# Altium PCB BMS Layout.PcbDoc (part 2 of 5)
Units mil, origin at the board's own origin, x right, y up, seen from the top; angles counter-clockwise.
Board outline 5576.78 x 4051.82 mil, 6 copper layers (Top Layer, GND1, Analog Signal, Power, GND2, Bottom Layer), stack 61.2 mil thick; 425 components, 206 nets, 1164 pads, 390 vias.
Unrouted connection lines stored in the file: 32.
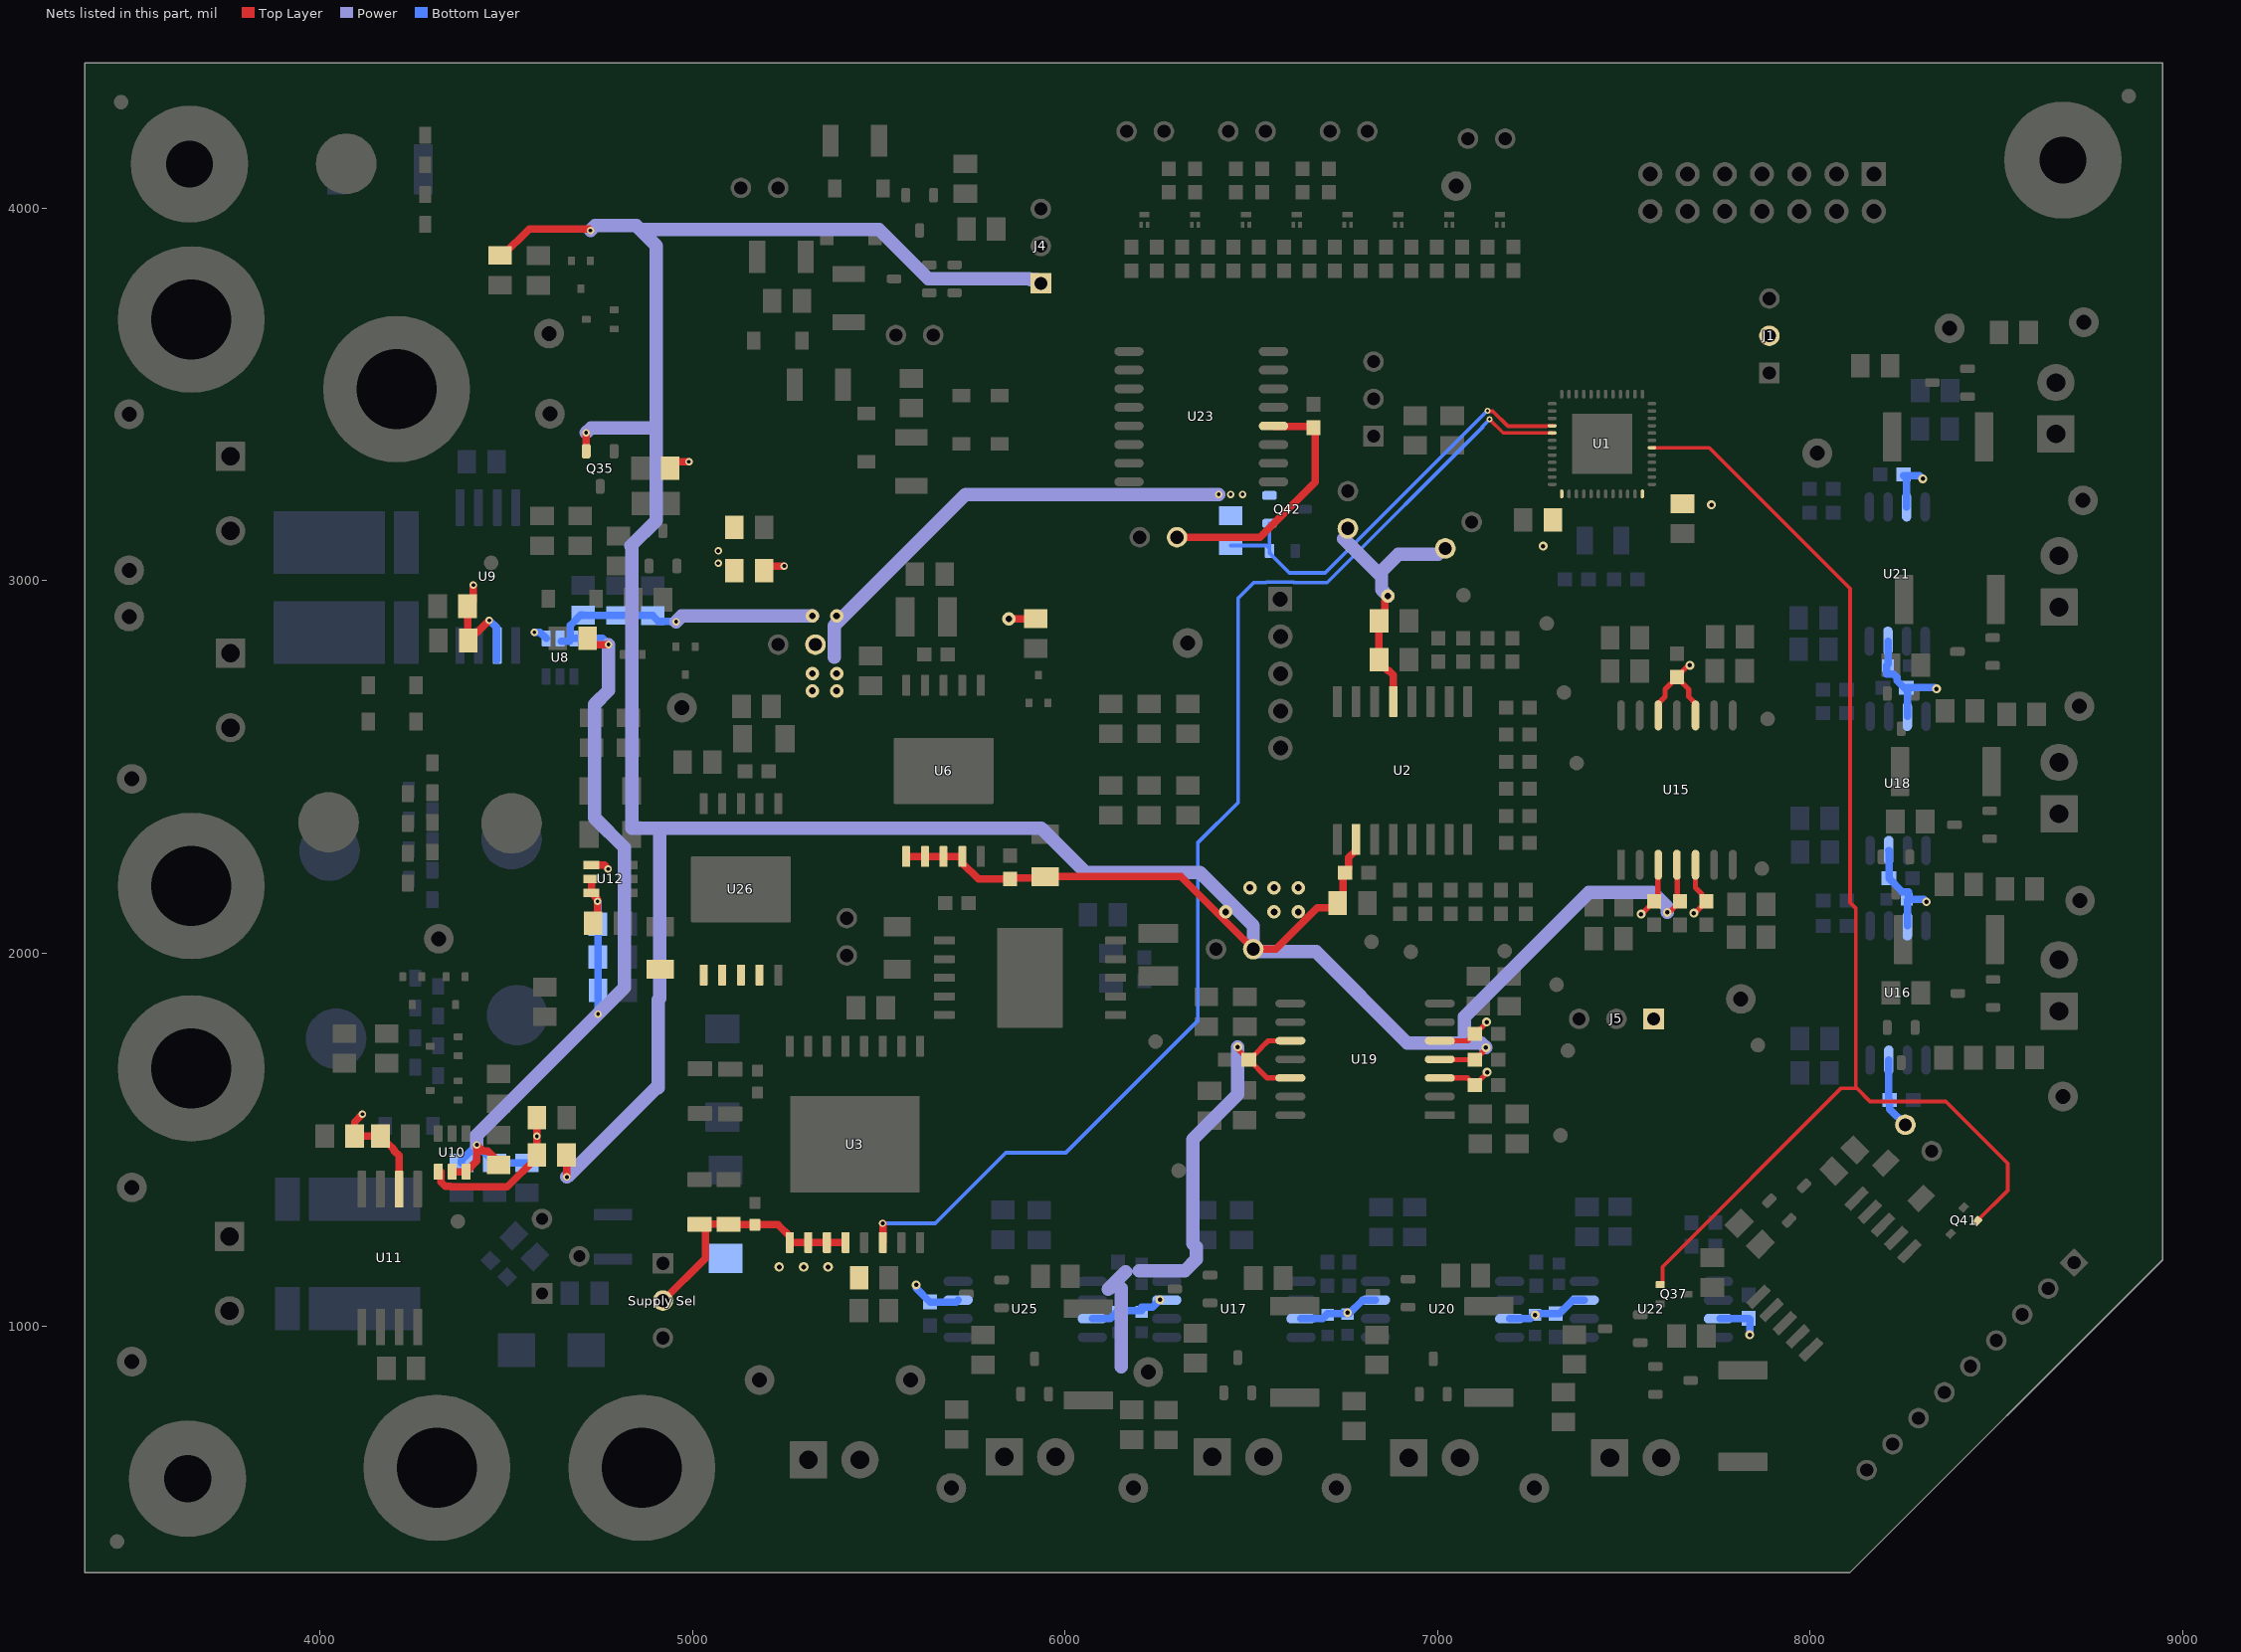
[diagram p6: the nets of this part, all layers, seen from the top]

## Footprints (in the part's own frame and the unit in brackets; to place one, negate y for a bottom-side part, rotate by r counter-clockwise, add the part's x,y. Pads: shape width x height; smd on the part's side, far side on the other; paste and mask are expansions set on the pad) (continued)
RGZ0048B_NV [mm] "QFN, 48-Leads, Body 7x7mm, Pitch 0.5mm, Thermal Pad 5.15x5.15mm, TI Recommended"
  oval 0.6x0.24 smd: 1(-3.4,2.75) 2(-3.4,2.25) 3(-3.4,1.75) 4(-3.4,1.25) 5(-3.4,0.75) 6(-3.4,0.25) 7(-3.4,-0.25) 8(-3.4,-0.75) 9(-3.4,-1.25) 10(-3.4,-1.75) 11(-3.4,-2.25) 12(-3.4,-2.75) 25(3.4,-2.75) 26(3.4,-2.25) 27(3.4,-1.75) 28(3.4,-1.25) 29(3.4,-0.75) 30(3.4,-0.25) 31(3.4,0.25) 32(3.4,0.75) 33(3.4,1.25) 34(3.4,1.75) 35(3.4,2.25) 36(3.4,2.75)
  oval 0.24x0.6 smd: 13(-2.75,-3.4) 14(-2.25,-3.4) 15(-1.75,-3.4) 16(-1.25,-3.4) 17(-0.75,-3.4) 18(-0.25,-3.4) 19(0.25,-3.4) 20(0.75,-3.4) 21(1.25,-3.4) 22(1.75,-3.4) 23(2.25,-3.4) 24(2.75,-3.4) 37(2.75,3.4) 38(2.25,3.4) 39(1.75,3.4) 40(1.25,3.4) 41(0.75,3.4) 42(0.25,3.4) 43(-0.25,3.4) 44(-0.75,3.4) 45(-1.25,3.4) 46(-1.75,3.4) 47(-2.25,3.4) 48(-2.75,3.4)
  rect 4.1x4.1 smd paste-2.575: 49(0,0)
  silkscreen extent -3.72,-3.72 3.72,3.72, body extent -3.57,-3.58 3.58,3.57, height 1.01
SOD-123 [mm] "On Semi recommended land pattern"
  rect 0.915x1.22 smd: 1(-1.637,0) 2(1.637,0)
  silkscreen extent -2.74,-1.17 2.03,1.17, body extent -1.93,-0.9 1.93,0.9, height 1.35
SOD-123FL [mm] "Copied from SOD-123"
  rect 0.915x1.22 smd: 1(-1.637,0) 2(1.637,0)
  silkscreen extent -2.74,-1.16 1.68,1.16, body extent -1.9,-0.9 1.9,0.9, height 1
SOT-23 [mm] "SOT23, 3-Leads, Body 2.9x1.3mm, Pitch 0.95mm, Lead Span 2.5mm, IPC Medium Density"
  rrect50% 1x0.6 smd: 1(-1.2,0.95) 2(-1.2,-0.95) 3(1.2,0)
  silkscreen extent -1.63,-1.5 0.7,1.5, body extent -1.16,-1.45 1.21,1.45, height 1
SOT-323 [mm] "Diodes Inc recommended land pattern.  2016-02-24"
  rrect21% 0.6x0.47 smd: 1(-0.95,0.65) 2(-0.95,-0.65) 3(0.95,0)
  silkscreen extent -1.14,-1.22 0.77,1.22, body extent -1.13,-1.13 1.12,1.12, height 1.13
TERM_BLK_ED555-2DS [mil]
  rrect4% 100x100 hole 50: 1(0,0)
  round 100 hole 50: 2(138,0)
  silkscreen extent -93,-161 215,113, body extent -69,-150 207,106, height 323
TI_Symbol_Overlay_Small [mil]
  silkscreen extent -90,-88 91,88
TP_SM_1MM [mm] "1mm Test Point, SMT"
  round 1 smd paste-0.5: 1(0,0)
TSW-105-07-X-S [mm] "Samtec 100mil, 1x5, 230 mil above insulator"
  rrect6% 1.65x1.65 hole 1.016: 1(-5.08,-0.025)
  round 1.65 hole 1.016: 2(-2.54,0) 3(0,0) 4(2.54,0) 5(5.08,0)
  silkscreen extent -7.05,-1.25 6.37,1.25, body extent -6.35,-1.27 6.35,1.27, height 8.38
WEEE_Minimum [mil] "WEEElie bin"
  silkscreen extent -95,-172 99,104
WSL3637_0.001 [mil] "Vishay WSL3637 recommended land pattern for 0.001 to 0.0019 Ohm"
  rect 168x300 smd: 1(-121,-45) 2(121,-45)
  rect 168x66 smd: 3(-121,162) 4(121,162)
  silkscreen extent -220,-210 220,210, body extent -185,-190 185,190, height 35
WSL3637_0_002 [mil] "Vishay WSL3637 recommended land pattern for 0.002 to 0.01 Ohm"
  rect 116x300 smd: 1(-147,-45) 2(147,-45)
  rect 116x66 smd: 3(-147,162) 4(147,162)
  silkscreen extent -220,-210 220,210, body extent -185,-190 185,190, height 35

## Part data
"12V Supply" Batt_1 Batt_2 Batt_3 Batt_4 Batt_5 Batt_6 Batt_7 Batt_8: library part CMP-0074913-1, "Terminal Block, 3.5mm Pitch, 2x1, TH", Color=Grey, Current_A=6A, Manufacturer="On-Shore Technology", Supplier Part Number 1=ED1514-ND, Voltage_V=150V
Batt Charger Load: library part CMP-0074910-1, "Terminal Block, 5.08 mm, 2x1, Brass, TH", Color=Blue, Current_A=15A, Manufacturer="On-Shore Technology", Supplier Part Number 1=ED1609-ND, Voltage_V=300V
Batt_ Charger_ GND GND_ Load_ LOAD_GND: library part CMP-0055166-1, "Standard Banana Jack, Uninsulated, 8.9mm", Manufacturer=Keystone, Supplier Part Number 1=36-575-8-ND
C1 C7: library part CMP-0007731-1, "CAP, CERM, 1 uF, 10 V, +/- 10%, X7R, 0805", Cap_Case=0805, Manufacturer=Kemet, Supplier Part Number 1=399-1172-1-ND, TempCo=X7R, Tolerance_%=10%, Value1="0.015 ohm", Value2=10V, ValueDisplayed=1uF
C2 C6 C8: library part CMP-0012474-2, "CAP, Film, 0.1 uF, 16 V, +/- 20%, 0805 SMD", Cap_Case=0805, Manufacturer=Panasonic, Supplier Part Number 1=PCF1126CT-ND, Tolerance_%=20%, Value1=Unknown, Value2=16V, ValueDisplayed=0.1uF
C3 C4: library part CMP-0006839-1, "CAP, CERM, 10 pF, 50 V, +/- 5%, C0G/NP0, 0603", Cap_Case=0603, Manufacturer=Kemet, Supplier Part Number 1=399-1049-1-ND, TempCo=C0G/NP0, Tolerance_%=5%, Value1=Unknown, Value2=50V, ValueDisplayed=10pF
C5: library part CMP-0079607-1, "CAP, CERM, 1 µF, 16 V,+/- 10%, X7R, AEC-Q200 Grade 1, 0603", Cap_Case=0603, Manufacturer=TDK, Supplier Part Number 1=445-12539-1-ND, TempCo=X7R, Tolerance_%=10%, Value2=16V, ValueDisplayed=1µF
C9: library part CMP-0007581-2, "CAP, CERM, 1000 pF, 50 V, +/- 1%, C0G/NP0, 0805", Cap_Case=0805, Manufacturer=AVX, Supplier Part Number 1=478-3759-1-ND, TempCo=C0G/NP0, Tolerance_%=1%, Value1="0.112 ohm", Value2=50V, ValueDisplayed=1000pF
C10 C14 C20 C22: library part CMP-0093201-1, "10 µF ±10% 50V Ceramic Capacitor X7R 1206 (3216 Metric)", Manufacturer="Cal-Chip Electronics", Operating Temperature Range="-55°C to +125°C", TempCo=15%, Temperature Characteristic=X7R, Tolerance_%=10%, ValueDisplayed=10uF
C11 C15 C17 C25 C26 C33 C114: library part CMP-0006861-3, "CAP, CERM, 0.1 uF, 50 V, +/- 10%, X7R, 0603", Cap_Case=0603, Manufacturer=Kemet, Supplier Part Number 1=399-5089-1-ND, TempCo=X7R, Tolerance_%=10%, Value1=Unknown, Value2=50V, ValueDisplayed=0.1uF
C12 C13: library part CMP-0094511-1, "0.1 µF ±5% 50V Ceramic Capacitor X7R 0603 (1608 Metric)", Digikey Part Number=478-7426-1-ND, Manufacturer="KYOCERA AVX", Mouser Part Number=581-06035C104J4Z2A, Operating Temperature Range=to, TempCo=15%, Temperature Characteristic=X7R, Tolerance_%=5%, ValueDisplayed=0.1uF
C16 C34 C79 C128: library part CMP-0082252-1, "CAP, CERM, 10 µF, 25 V,+/- 20%, X7R, AEC-Q200 Grade 1, 1206", Cap_Case=1206, Manufacturer=MuRata, Supplier Part Number 1=490-6519-1-ND, TempCo=X7R, Tolerance_%=20%, Value2=25V, ValueDisplayed=10µF
C18: library part CMP-2000-06366-1, "Chip Capacitor, 1 uF, +/- 10%, 100 V, -55 to 125 degC, 1210 (3225 Metric), RoHS, Tape and Reel GRM32ER72A105KA01L", Capacitance=1µF, Manufacturer=Murata, Operating Temperature=-55°C~125°C, Package / Case=1210(3225Metric), Package Description="2-Pin Surface Mount Device, Body 3.2 x 2.5 mm", Package Reference=1210, Ratings=-, Standard Package=1, Temperature Coefficient=X7R, Tolerance=±10%, Voltage - Rated=100V
C19 C27: library part CMP-0009190-1, "CAP, CERM, 10 uF, 25 V, +/- 10%, X7R, 1210", Cap_Case=1210, Manufacturer=MuRata, Supplier Part Number 1=490-1867-1-ND, TempCo=X7R, Tolerance_%=10%, Value1=Unknown, Value2=25V, ValueDisplayed=10uF
C21 C23: library part CMP-0093169-1, "150µF Molded Tantalum Polymer Capacitor 20V 2917 (7343 Metric) 50mOhm @ 100kHz", Digikey Part Number=399-19581-1-ND, Leakage Current=300uA, Manufacturer=Kemet, Mouser Part Number=80-T521D157M020ATE50, Operating Temperature Range="-55°C to +105°C", Tolerance_%=20%, ValueDisplayed=150uF
C24: library part CMP-0011596-1, "CAP, TA, 1 uF, 50 V, +/- 10%, 4.6 ohm, SMD", Cap_Case=C, Manufacturer=Vishay-Sprague, Supplier Part Number 1=718-1041-1-ND, Tolerance_%=10%, Value1="4.6 ohm", Value2=50V, ValueDisplayed=1uF
C28 C29 C124 C125 C126: library part CMP-0009164-1, "CAP, CERM, 10 uF, 50 V, +/- 10%, X7S, AEC-Q200 Grade 1, 1210", Cap_Case=1210_280, Manufacturer=TDK, Supplier Part Number 1=445-7004-1-ND, TempCo=X7S, Tolerance_%=10%, Value1="0.002827 ohm", Value2=50V, ValueDisplayed=10uF
C30 C31 C32: library part CMP-0007632-2, "CAP, CERM, 0.1 uF, 50 V, +/- 10%, X7R, 0805", Cap_Case=0805, Manufacturer=AVX, Supplier Part Number 1=478-1395-1-ND, TempCo=X7R, Tolerance_%=10%, Value1="0.024 ohm", Value2=50V, ValueDisplayed=0.1uF
C35 C36: library part CMP-0007900-2, "CAP, CERM, 1 pF, 50 V, +/- 25%, C0G/NP0, 0805", Cap_Case=0805, Manufacturer="Yageo America", Supplier Part Number 1=311-1089-1-ND, TempCo=C0G/NP0, Tolerance_%=25%, Value1=Unknown, Value2=50V, ValueDisplayed=1pF
C37 C40 C42 C45 C47: library part CMP-0008021-2, "CAP, CERM, 0.1 uF, 50 V, +/- 10%, X7R, AEC-Q200 Grade 1, 0805", Cap_Case=0805, Manufacturer=MuRata, Supplier Part Number 1=490-8049-1-ND, TempCo=X7R, Tolerance_%=10%, Value1=Unknown, Value2=50V, ValueDisplayed=0.1uF
C38 C43 C48: library part CMP-0007706-2, "CAP, CERM, 100 pF, 100 V, +/- 5%, X7R, 0805", Cap_Case=0805, Manufacturer=Kemet, Supplier Part Number 1=80-C0805C101J1R, TempCo=X7R, Tolerance_%=5%, Value1=Unknown, Value2=100V, ValueDisplayed=100pF
C39 C44 C49: library part CMP-0080480-1, "CAP, CERM, 1 µF, 50 V,+/- 20%, X7R, AEC-Q200 Grade 1, 0805", Cap_Case=0805, Manufacturer=MuRata, Supplier Part Number 1=490-16470-1-ND, TempCo=X7R, Tolerance_%=20%, Value2=50V, ValueDisplayed=1µF
C41 C46 C53: library part CMP-0008408-2, "CAP, CERM, 0.01 uF, 250 V, +/- 10%, X7R, 0805", Cap_Case=0805, Manufacturer="Taiyo Yuden", Supplier Part Number 1=587-1271-1-ND, TempCo=X7R, Tolerance_%=10%, Value1=Unknown, Value2=250V, ValueDisplayed=0.01uF
C51 C52: library part CMP-0080090-1, "CAP, CERM, 500 pF, 50 V,+/- 2%, C0G/NP0, 0805", Cap_Case=0805, Manufacturer=AVX, Supplier Part Number 1=478-10532-1-ND, TempCo=C0G/NP0, Tolerance_%=2%, Value2=50V, ValueDisplayed=500pF
C84 C85 C92 C93 C97 C101 C102 C106: library part CMP-0008323-2, "CAP, CERM, 1 uF, 16 V, +/- 10%, X7R, 0805", Cap_Case=0805, Manufacturer=MuRata, Supplier Part Number 1=490-1691-1-ND, TempCo=X7R, Tolerance_%=10%, Value1="0.003 ohm", Value2=16V, ValueDisplayed=1uF
C86 C89 C94 C98 C103 C108 C111 C152: library part CMP-0006797-3, "CAP, CERM, 680 pF, 50 V, +/- 1%, C0G/NP0, 0603", Cap_Case=0603, Manufacturer=AVX, Supplier Part Number 1=478-6033-1-ND, TempCo=C0G/NP0, Tolerance_%=1%, Value1=Unknown, Value2=50V, ValueDisplayed=680pF
C87 C90 C95 C99 C104 C107 C109 C153 C154: library part CMP-0007078-4, "CAP, CERM, 0.1 uF, 50 V, +/- 10%, X7R, AEC-Q200 Grade 1, 0603", Cap_Case=0603, Manufacturer=TDK, Supplier Part Number 1=445-5666-1-ND, TempCo=X7R, Tolerance_%=10%, Value1="0.0296 ohm", Value2=50V, ValueDisplayed=0.1uF
C88 C91 C96 C100 C105 C110 C133 C134 C135 C136 C137 C138 C139 C140 C141 C142 C143 C144 C145 C146 C147 C148 C149 C150 C151 C155 C160: library part CMP-0007006-2, "CAP, CERM, 1 uF, 25 V, +/- 10%, X5R, 0603", Cap_Case=0603, Manufacturer=TDK, Supplier Part Number 1=445-5146-1-ND, TempCo=X5R, Tolerance_%=10%, Value1=Unknown, Value2=25V, ValueDisplayed=1uF
C112: library part CMP-0008651-1, "CAP, CERM, 68 uF, 10 V, +/- 20%, X5R, 1206_190", Cap_Case=1206_190, Manufacturer=TDK, Supplier Part Number 1=445-14673-1-ND, TempCo=X5R, Tolerance_%=20%, Value1="0.003494 ohm", Value2=10V, ValueDisplayed=68uF
C115 C116 C117 C118 C119 C120 C121 C156: library part CMP-0006843-4, "CAP, CERM, 1000 pF, 50 V, +/- 5%, C0G/NP0, 0603", Cap_Case=0603, Manufacturer=Kemet, Supplier Part Number 1=399-3293-1-ND, TempCo=C0G/NP0, Tolerance_%=5%, Value1=Unknown, Value2=50V, ValueDisplayed=1000pF
C122 C123: library part CMP-0007632-1, "CAP, CERM, 0.1 uF, 50 V, +/- 10%, X7R, 0805", Cap_Case=0805, Manufacturer=AVX, Supplier Part Number 1=478-1395-1-ND, TempCo=X7R, Tolerance_%=10%, Value1="0.024 ohm", Value2=50V, ValueDisplayed=0.1uF
C164: library part CMP-0091091-1, "Cap Ceramic 0.001uF 250V X7R 10% Pad SMD 0805 Soft Termination 125C Automotive T/R", Digikey Part Number=490-5589-1-ND, Manufacturer=Murata, Mouser Part Number=81-GCJ21AR72E102KX1D, Operating Temperature Range="-55°C to +125°C", TempCo=15%, Temperature Characteristic=X7R, Tolerance_%=10%, ValueDisplayed=1000pF
D1 D2 D3 D7 D8 D9 D10: library part CMP-0077083-2, "Diode, Standard Recovery Rectifier, 200 V, 1 A, SOD-123FL", Manufacturer="Micro Commercial Components", Value1=1A, Value2=1.1V
D4 D5 D6: library part CMP-0005805-3, "Diode, Zener, 6.2 V, 500 mW, SOD-123", Manufacturer="Diodes Inc.", Power_W=500mW, Value1=0.5W
FID1 FID2 FID3: library part CMP-0077181-1, "Fiducial mark.  There is nothing to buy or mount.", Manufacturer=N/A
H1 H2 H4: library part CMP-0003617-1, "Machine Screw, Round, #4-40 x 1/4, Nylon, Philips panhead", Manufacturer="B&F Fastener Supply", Supplier Part Number 1=H542-ND
H5 H6 H8: library part CMP-0003610-1, "Standoff, Hex, 0.5\"L #4-40 Nylon", Manufacturer=Keystone, Supplier Part Number 1=36-1902C-ND
I2C_pull J_1V85 J_2V5 J_3V3 J_3V3_2 J_5V J_heater J_LS J_pump J_PWM Sensor1 Sensor2 Sensor3: library part CMP-0075049-1, "Header, 2.54mm, 2x1, Gold, TH", Manufacturer="Fischer Elektronik"
J1 J4 J5 J6 "Supply Sel": library part CMP-0075048-1, "Header, 2.54mm, 3x1, Gold, TH", Manufacturer="Fischer Elektronik"
J2: library part CMP-0075411-1, "Header, 100mil, 5x1, Gold, TH", Color=Black, Current_A=6.3A, Manufacturer=Samtec, Supplier Part Number 1=SAM1029-05-ND, Voltage_V=550V
J3: library part CMP-0097746-1, "Connector Header Through Hole, Right Angle 9 position 0.098\" (2.50mm)", Current_A=3A, Digikey Part Number=455-2224-ND, Manufacturer=JST, Operating Temperature Range="-25°C to +85°C", Voltage_V=250V
JTAG: library part CMP-0054695-2, "Header (shrouded), 100 mil, 7x2, Gold, TH", Manufacturer="Sullins Connector Solutions", Supplier Part Number 1=S9170-ND
LBL1: library part CMP-0003625-1, "Thermal Transfer Printable Labels, 0.650\" W x 0.200\" H - 10,000 per roll", Manufacturer=Brady, Supplier Part Number 1=97C5133
Logo1: library part CMP-0074844-1
Logo2: library part CMP-0074838-1, "Texas Instrument Corporate Signature"
Logo3: library part CMP-0074847-1, "FCC_disclaimer"
Logo4: library part CMP-0074769-1
Q1 Q2 Q5 Q7 Q9 Q12 Q14: library part CMP-0000353-2, "Transistor, PNP, 40 V, 3 A, SOT-23", Manufacturer="Diodes Inc.", Supplier Part Number 1=ZXTP25040DFHCT-ND, Value1="3 A", Value2=900
Q3 Q4 Q6 Q8 Q10 Q13 Q15 Q32 Q34 Q38 Q49: library part CMP-0000451-1, "Transistor, NPN, 100 V, 1 A, SOT-23", Manufacturer="NXP Semiconductor", Supplier Part Number 1=568-4344-1-ND, Value1="1 A", Value2=500
Q11 Q25 Q26 Q27 Q28 Q29 Q30 Q31: library part CMP-0000409-2, "Transistor, NPN, 40 V, 0.2 A, 3-UFDFN", Manufacturer="Diodes Inc.", Supplier Part Number 1=MMBT3904LP-7BDICT-ND, Value1="0.2 A", Value2=400
Q17 Q18 Q19 Q20 Q21 Q22 Q23: library part CMP-0093493-1, "N-Channel 60 V 200A (Tc) 150W (Tc) Surface Mount PowerPAK® 8 x 8", Digikey Part Number=SQJQ466E-T1_GE3CT-ND, Drain To Source Breakdown Voltage=60V, Input Capacitace At Vds="8170pF @ 25V", Manufacturer=Vishay, Mouser Part Number=78-SQJQ466E-T1_GE3, Operating Temperature Range="-55°C to +175°C", Power_W=150W, Pulse Drain Current=500A, Typ Forward Diode Voltage=0.82V
Q24 Q37 Q39 Q40 Q41 Q43 Q44 Q45 Q46 Q47 Q48 Q50: library part CMP-0000774-1, "MOSFET, N-CH, 60 V, 0.31 A, SOT-323", Alternate Manufacturer=None, Manufacturer="Fairchild Semiconductor", Supplier Part Number 1=2N7002KWCT-ND, Value1=1
Q33 Q35: library part CMP-0000344-1, "Transistor, PNP, 60 V, 0.6 A, SOT-23", Manufacturer="ON Semiconductor", Supplier Part Number 1=MMBT2907ALT1GOSCT-ND, Value1="0.6 A"
Q36 Q42: library part CMP-0000095-3, "MOSFET, P-CH, -80 V, -1.2 A, SOT-23", Alternate Manufacturer=None, Manufacturer=Vishay-Siliconix, Value2="11 nC"
R1 R120: library part CMP-0020620-3, "RES, 10 k, 5%, 0.125 W, AEC-Q200 Grade 0, 0805", Manufacturer=Panasonic, Power_W=125mW, Supplier Part Number 1=P10KACT-ND, TempCo="200 ppm/C", Tolerance_%=5%, Value2=0.125W, Value_Code=10k0, ValueDisplayed=10k
R2 R82 R84 R90 R93 R98 R102 R141 R142: library part CMP-0018856-2, "RES, 10.0 k, 0.1%, 0.125 W, 0805", Manufacturer="Susumu Co Ltd", Power_W=125mW, Supplier Part Number 1=RG20P10.0KBCT-ND, TempCo="25 ppm/C", Tolerance_%=0.1%, Value2=0.125W, Value_Code=10k0, ValueDisplayed=10.0k
R3 R83 R86 R91 R95 R99 R103 R107: library part CMP-0023298-5, "RES, 84.5, 1%, 0.1 W, 0603", Manufacturer=Yageo, Power_W=100mW, Supplier Part Number 1=311-84.5HRCT-ND, TempCo="100 ppm/C", Tolerance_%=1%, Value2=0.1W, Value_Code=84R5, ValueDisplayed=84.5
R4 R85 R87 R89 R94 R97 R101: library part CMP-0020028-2, "RES, 3.01 k, 0.1%, 0.125 W, 0805", Manufacturer="Yageo America", Power_W=125mW, TempCo="25 ppm/C", Tolerance_%=0.1%, Value2=0.125W, Value_Code=3k01, ValueDisplayed=3.01k
R5 R88 R92 R96 R100 R104 R109: library part CMP-0019899-2, "RES, 2.05 k, 0.1%, 0.125 W, 0805", Manufacturer="Yageo America", Power_W=125mW, Supplier Part Number 1=9982892, TempCo="25 ppm/C", Tolerance_%=0.1%, Value2=0.125W, Value_Code=2k05, ValueDisplayed=2.05k
R6 R112 R113 R114 R115 R116 R117 R118: library part CMP-0023919-1, "RES, 1.00 k, 0.1%, 0.1 W, 0603", Manufacturer="Yageo America", Power_W=100mW, Supplier Part Number 1=603-RT0603BRD071KL, TempCo="25 ppm/C", Tolerance_%=0.1%, Value2=0.1W, Value_Code=1k00, ValueDisplayed=1.00k
R7 R9 R14 R24 R25 R28 R29 R30 R31 R34 R35 R36 R38 R39 R75: library part CMP-0021282-3, "RES, 499, 1%, 0.125 W, AEC-Q200 Grade 0, 0805", Manufacturer=Vishay-Dale, Power_W=125mW, Supplier Part Number 1=541-499CCT-ND, TempCo="100 ppm/C", Tolerance_%=1%, Value2=0.125W, Value_Code=499R, ValueDisplayed=499
R8 R26 R27 R32 R33 R37 R40 R43: library part CMP-0095213-1, "RES Thick Film, 24.9Ω, 1%, 1.5W, 100ppm/°C, 2512", Manufacturer="Vishay Dale", Operating Temperature Range="-55°C to +155°C", Power_W=1.5W, TempCo=100ppm/°C, Tolerance_%=1%
R10: library part CMP-0018857-1, "RES, 100 k, 0.1%, 0.125 W, 0805", Manufacturer="Susumu Co Ltd", Power_W=125mW, Supplier Part Number 1=RG20P100KBCT-ND, TempCo="25 ppm/C", Tolerance_%=0.1%, Value2=0.125W, Value_Code=100k
R11: library part CMP-0018936-1, "RES, 2.61 k, 0.1%, 0.125 W, 0805", Manufacturer="Susumu Co Ltd", Power_W=125mW, Supplier Part Number 1=RG20P2.61KBCT-ND, TempCo="25 ppm/C", Tolerance_%=0.1%, Value2=0.125W, Value_Code=2k61, ValueDisplayed=2.61k
R12: library part CMP-0018855-2, "RES, 1.00 k, 0.1%, 0.125 W, 0805", Manufacturer="Susumu Co Ltd", Power_W=125mW, Supplier Part Number 1=RG20P1.0KBCT-ND, TempCo="25 ppm/C", Tolerance_%=0.1%, Value2=0.125W, Value_Code=1k00, ValueDisplayed=1.00k
R13: library part CMP-0019773-1, "RES, 20.0 k, 0.1%, 0.125 W, 0805", Manufacturer="Yageo America", Power_W=125mW, Supplier Part Number 1=9982892, TempCo="25 ppm/C", Tolerance_%=0.1%, Value2=0.125W, Value_Code=20k0, ValueDisplayed=20.0k
R15: library part CMP-0020383-2, "RES, 8.25 k, 0.1%, 0.125 W, 0805", Manufacturer="Yageo America", Power_W=125mW, TempCo="25 ppm/C", Tolerance_%=0.1%, Value2=0.125W, Value_Code=8k25, ValueDisplayed=8.25k
R16: library part CMP-0020279-2, "RES, 6.49 k, 0.1%, 0.125 W, 0805", Manufacturer="Yageo America", Power_W=125mW, TempCo="25 ppm/C", Tolerance_%=0.1%, Value2=0.125W, Value_Code=6k49, ValueDisplayed=6.49k
R17: library part CMP-0020387-2, "RES, 8.66 k, 0.1%, 0.125 W, 0805", Manufacturer="Yageo America", Power_W=125mW, TempCo="25 ppm/C", Tolerance_%=0.1%, Value2=0.125W, Value_Code=8k66, ValueDisplayed=8.66k
R18: library part CMP-0019900-1, "RES, 2.08 k, 0.1%, 0.125 W, 0805", Manufacturer="Yageo America", Power_W=125mW, Supplier Part Number 1=9982892, TempCo="25 ppm/C", Tolerance_%=0.1%, Value2=0.125W, Value_Code=2k08, ValueDisplayed=2.08k
R19: library part CMP-0018992-2, "RES, 4.70 k, 0.1%, 0.125 W, 0805", Manufacturer="Susumu Co Ltd", Power_W=125mW, Supplier Part Number 1=RG20P4.7KBCT-ND, TempCo="25 ppm/C", Tolerance_%=0.1%, Value2=0.125W, Value_Code=4k70, ValueDisplayed=4.70k
R20: library part CMP-0018896-1, "RES, 16.0 k, 0.1%, 0.125 W, 0805", Manufacturer="Susumu Co Ltd", Power_W=125mW, Supplier Part Number 1=RG20P16.0KBCT-ND, TempCo="25 ppm/C", Tolerance_%=0.1%, Value2=0.125W, Value_Code=16k0, ValueDisplayed=16.0k
R21: library part CMP-0020510-3, "RES, 2.0 k, 5%, 0.125 W, AEC-Q200 Grade 0, 0805", Manufacturer=Vishay-Dale, Power_W=125mW, Supplier Part Number 1=541-2.0KACT-ND, TempCo="200 ppm/C", Tolerance_%=5%, Value2=0.125W, Value_Code=2k00, ValueDisplayed=2.0k
R22 R66 R67: library part CMP-0020801-3, "RES, 0, 5%, 0.125 W, 0805", Manufacturer=Rohm, Power_W=125mW, Supplier Part Number 1=RHM0.0ACT-ND, TempCo="400 ppm/C", Tolerance_%=5%, Value2=0.125W, Value_Code=0000, ValueDisplayed=0
R23: library part CMP-0020426-1, "RES, 9.31 k, 0.1%, 0.125 W, 0805", Manufacturer="Yageo America", Power_W=125mW, TempCo="25 ppm/C", Tolerance_%=0.1%, Value2=0.125W, Value_Code=9k31, ValueDisplayed=9.31k
R41 R42 R45 R47 R48 R50 R51 R53 R63: library part CMP-0020842-3, "RES, 10.0 k, 1%, 0.125 W, AEC-Q200 Grade 0, 0805", Manufacturer=Vishay-Dale, Power_W=125mW, Supplier Part Number 1=541-10.0KCCT-ND, TempCo="100 ppm/C", Tolerance_%=1%, Value2=0.125W, Value_Code=10k0, ValueDisplayed=10.0k
R44: library part CMP-0086260-1, "RES, 0, 3 W, 2512", Manufacturer="TE Connectivity", Power_W=3W, Tolerance_%=0%, Value_Code=0000, ValueDisplayed=0
R46 R54: library part CMP-0020087-2, "RES, 44.2 k, 0.1%, 0.125 W, 0805", Manufacturer="Yageo America", Power_W=125mW, TempCo="25 ppm/C", Tolerance_%=0.1%, Value2=0.125W, Value_Code=44k2, ValueDisplayed=44.2k
R49 R52 R56 R105 R124 R140: library part CMP-0018857-2, "RES, 100 k, 0.1%, 0.125 W, 0805", Manufacturer="Susumu Co Ltd", Power_W=125mW, Supplier Part Number 1=RG20P100KBCT-ND, TempCo="25 ppm/C", Tolerance_%=0.1%, Value2=0.125W, Value_Code=100k
R55: library part CMP-0018027-2, "RES, 1.00 M, 1%, 0.25 W, 1206", Manufacturer="Yageo America", Power_W=250mW, Supplier Part Number 1=311-1.00MFRCT-ND, TempCo="100 ppm/C", Tolerance_%=1%, Value2=0.25W, Value_Code=1M00, ValueDisplayed=1.00M
R57 R59: library part CMP-0020273-2, "RES, 6.04 k, 0.1%, 0.125 W, 0805", Manufacturer="Yageo America", Power_W=125mW, TempCo="25 ppm/C", Tolerance_%=0.1%, Value2=0.125W, Value_Code=6k04, ValueDisplayed=6.04k
R58: library part CMP-0017675-3, "RES, 61.9 k, 1%, 0.25 W, AEC-Q200 Grade 0, 1206", Manufacturer=Panasonic, Power_W=250mW, Supplier Part Number 1=P61.9KFCT-ND, TempCo="100 ppm/C", Tolerance_%=1%, Value2=0.25W, Value_Code=61k9, ValueDisplayed=61.9k
R60 R61 R64 R65 R68 R70 R72: library part CMP-0079710-1, "RES, 49.9, 1%, 0.15 W, 0805", Manufacturer="TT Electronics/IRC", Power_W=150mW, TempCo="100 ppm/C", Tolerance_%=1%, Value2=0.15W, Value_Code=49R9, ValueDisplayed=49.9
R106: library part CMP-0019938-2, "RES, 30.1 k, 0.1%, 0.125 W, 0805", Manufacturer="Yageo America", Power_W=125mW, TempCo="25 ppm/C", Tolerance_%=0.1%, Value2=0.125W, Value_Code=30k1, ValueDisplayed=30.1k
R108: library part CMP-0020263-2, "RES, 68.1 k, 0.1%, 0.125 W, 0805", Manufacturer="Yageo America", Power_W=125mW, TempCo="25 ppm/C", Tolerance_%=0.1%, Value2=0.125W, Value_Code=68k1, ValueDisplayed=68.1k
R110 R111: library part CMP-0020740-1, "RES, 5.1 k, 5%, 0.125 W, 0805", Manufacturer=Panasonic, Power_W=125mW, Supplier Part Number 1=P5.1KACT-ND, TempCo="200 ppm/C", Tolerance_%=5%, Value2=0.125W, Value_Code=5k10, ValueDisplayed=5.1k
R119: library part CMP-0020445-1, "RES, 100, 5%, 0.125 W, 0805", Manufacturer=Vishay-Dale, Power_W=125mW, Supplier Part Number 1=541-100ACT-ND, TempCo="200 ppm/C", Tolerance_%=5%, Value2=0.125W, Value_Code=100R, ValueDisplayed=100
R128 R129 R130 R131 R132 R133: library part CMP-0025884-1, "RES, 0, 5%, 0.125 W, 0603", Manufacturer=Vishay/Beyschlag, Power_W=125mW, Supplier Part Number 1=MCT0603-0.0-ZZCT-ND, TempCo=ppm/C, Tolerance_%=5%, Value2=0.125W, Value_Code=0000, ValueDisplayed=0
R139: library part CMP-0020433-1, "RES, 20.0 k, 0.5%, 0.125 W, 0805", Manufacturer="Yageo America", Power_W=125mW, TempCo="50 ppm/C", Tolerance_%=0.5%, Value2=0.125W, Value_Code=20k0, ValueDisplayed=20.0k
R143: library part CMP-0018952-2, "RES, 30.0 k, 0.1%, 0.125 W, 0805", Manufacturer="Susumu Co Ltd", Power_W=125mW, Supplier Part Number 1=RG20P30.0KBCT-ND, TempCo="25 ppm/C", Tolerance_%=0.1%, Value2=0.125W, Value_Code=30k0, ValueDisplayed=30.0k
Rshunt1: library part CMP-0015291-2, "RES, 0.001, 1%, 3 W, WSL3637", Manufacturer=Vishay-Dale, Power_W=3W, Supplier Part Number 1=46P3685, TempCo="75 ppm/C", Tolerance_%=1%, Value_Code=1L000, ValueDisplayed=0.001
Rshunt2: library part CMP-0082607-1, "RES, 0.003, 1%, 3 W, AEC-Q200 Grade 0, 9.14x9.4mm", Manufacturer=Vishay-Dale, Power_W=3W, Supplier Part Number 1=WSLI-.003CT-ND, TempCo="50 ppm/C", Tolerance_%=1%, Value_Code=3L000, ValueDisplayed=0.003
TP1: library part CMP-0055137-2, "Test Point, Miniature, Red, TH", Color=Red, Manufacturer="Keystone Electronics", Supplier Part Number 1=36-5000-ND
TP2 TP3 TP4 TP5 TP6 TP8 TP9 TP10: library part CMP-0055138-2, "Test Point, Miniature, Black, TH", Color=Black, Manufacturer="Keystone Electronics", Supplier Part Number 1=36-5001-ND
TP7 TP12 TP13 TP14 TP15 TP17 TP18 TP25 TP26 TP27 TP28 TP29 TP30 TP32 TP40 TP45 TP46: library part CMP-0003825-1, "1mm Test Point, SMT", Manufacturer=Any
TP11: library part CMP-0055138-1, "Test Point, Miniature, Black, TH", Color=Black, Manufacturer=Keystone, Supplier Part Number 1=36-5001-ND
TP16 TP22 TP23 TP24 TP33 TP34 TP35 TP36 TP37 TP38 TP39: library part CMP-0055137-1, "Test Point, Miniature, Red, TH", Color=Red, Manufacturer=Keystone, Supplier Part Number 1=36-5000-ND
TP19 TP20 TP21 TP31 TP41 TP43: library part CMP-0055164-1, "Test Point, Miniature, Green, TH", Color=Green, Manufacturer=Keystone, Supplier Part Number 1=36-5116-ND
U1: library part CMP-0076614-1, "MSP430FR59691 16 MHz Ultra-Low-Power Microcontroller featuring 64 KB FRAM, 2 KB SRAM, 40 IO, RGZ0048B (VQFN-48)", Alternate Manufacturer="Texas Instruments", Alternate PartNumber=MSP430FR59691IRGZT, PartNumber=MSP430FR5969-SP
U2: library part CMP-0067762-2, "3V LVDS Quad CMOS Differential Line Driver, NAC0016A (CFP-16)", Manufacturer="Texas Instruments", PartNumber=ADC128S102QML-SP
U3: library part CMP-0860518-2, "Radiation Hardened 7-V, 6-A Load Switch, HKR0016A (CFP-16)", Alternate Manufacturer="Texas Instruments", PartNumber=TPS7H2211-SP
U4 U6 U26: library part CMP-0067526-3, "Wide Vin Low-Dropout Voltage Regulator, HKU0010A (CFP-10)", Alternate Manufacturer="Texas Instruments", Operating Temperature Range="25 to 25 C", PartNumber=TPS7A4501-SP, Rating=Space
U5: library part CMP-0062-00013-3, "3-Terminal Adjustable Regulator, 3-pin TO-39", Manufacturer="Texas Instruments", PackageTopMarking="NSZSSXXYYA 5962R99517*05VXA LM117HRLQV Q", PowerWise=N
U7: library part CMP-0088839-1, "Precision Micropower Shunt Voltage Reference", Manufacturer="Texas Instruments", Mouser Part Number=595-LM4050WG2.5-MPR, Nominal Supply Current=40.5uA, Operating Temperature Range="to +25°C", Output Voltage=2.5V, PartNumber=LM4050QML-SP
U8 U10 U12: library part CMP-0036814-1, "Radiation-Tolerant High-Speed Comparator with 3.5ns Propagation Delay", Input Bias Current=1uA, Input Offset Voltage=0.5mV, Manufacturer="Texas Instruments", Max Supply Voltage=5.5V, Min Supply Voltage=2.4V, Nominal Supply Current=5.7mA, Operating Temperature Range="-55°C to +125°C", Output Current Per Channel=30mA, PartNumber=TLV1H103-SP
U9 U11: library part CMP-0081563-2, "Voltage Output, Unidirectional Measurement Current-Shunt Monitor, HKX0008A (CFP-8)", Alternate Manufacturer="Texas Instruments", PartNumber=INA901-SP, Rating=Space
U15 U19: library part CMP-0089209-1, "Precision, CMOS Input, RRIO, Wide Supply Range Amplifiers", Input Bias Current=0.0000002uA, Input Offset Voltage=0.037mV, Manufacturer="Texas Instruments", Max Dual Supply Voltage=12V, Min Dual Supply Voltage=2.7V, Nominal Supply Current=4.5-4.6mA, Operating Temperature Range="-40°C to +125°C", Output Current Per Channel=42-84mA, Voltage Gain=134dB
U16 U17 U18 U20 U21 U22 U25: library part CMP-0096976-1, "Radiation-Hardened, High Common-Mode Voltage Difference Amplifier", Input Offset Voltage=0.35mV, Manufacturer="Texas Instruments", Max Dual Supply Voltage=9V, Max Supply Voltage=18V, Min Dual Supply Voltage=2V, Min Supply Voltage=4V, Nominal Supply Current=810uA, Operating Temperature Range="-55°C to +150°C", Output Current Per Channel=25mA, Voltage Gain=0.001V/mV
U23: library part CMP-0097071-1, "9-Channel (8-Remote and 1-Local), High-Accuracy Temperature Sensor", Manufacturer="Texas Instruments", Max Supply Voltage=3.6V, Min Supply Voltage=1.7V, Mouser Part Number=595-5962R2021401VXC, Operating Temperature Range="-55°C to +125°C", PartNumber=TMP9R00-SP
Y1: library part CMP-0089623-1, "32.768kHz ±10ppm Crystal 9pF 80 kOhms 2-SMD, No Lead , Automotive AEC-Q200", Digikey Part Number=XC2160CT-ND, Frequency Tolerance=10ppm, Frequency_Fixed=32.768kHz, Load Capacitance=9pF, Manufacturer="ECS Inc.", Mouser Part Number=520-.327-9-34QCST, Operating Temperature Range="-40°C to +125°C"

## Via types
v1: diameter 20, hole 10, Top Layer to Bottom Layer, tented both sides, 113 vias
v2: diameter 24, hole 12, Top Layer to Bottom Layer, tented both sides, 103 vias
v3: diameter 19.68, hole 7.87, Top Layer to Bottom Layer, 93 vias
v4: diameter 36, hole 18, Top Layer to Bottom Layer, 46 vias
v5: diameter 36, hole 18, Top Layer to Bottom Layer, tented both sides, 12 vias
v6: diameter 16, hole 8, Top Layer to Bottom Layer, tented both sides, 10 vias
v7: diameter 26, hole 13, Top Layer to Bottom Layer, tented both sides, 7 vias
v8: diameter 32, hole 16, Top Layer to Bottom Layer, tented both sides, 3 vias
v9: diameter 28, hole 14, Top Layer to Bottom Layer, tented both sides, 2 vias
v10: diameter 20, hole 12, Top Layer to Bottom Layer, tented both sides, 1 vias

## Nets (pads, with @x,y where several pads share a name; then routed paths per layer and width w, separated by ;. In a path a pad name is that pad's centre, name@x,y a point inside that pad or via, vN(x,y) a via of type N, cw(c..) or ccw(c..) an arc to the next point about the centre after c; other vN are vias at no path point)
0.6V: R46.1 R57.2 U10.4 | length 437
  Top Layer w20: U10.4@4317.52,1413.82 4325.11,1413.82 4325.11,1385.88 4336.83,1374.16 4350.13,1374.16 4351.69,1372.61 4502.07,1372.61 4581.99,1452.52 R46.1@4581.99,1459.02 ; R46.1@4582.26,1466.64 R57.2@4582.26,1566.15
  other v1: 4582.12,1508.85
0V6: R54.1 R59.2 U8.4 | length 38.6
  Bottom Layer w20: v1(4575.61,2861.71) 4590.48,2861.71 U8.4@4607.23,2844.97
  other v1: 5068.9,3047.39 5068.9,3079.87
1.89V: C114.2 J_1V85.1 U23.12 | length 689.1
  Top Layer w20: J_1V85.1@6300.39,3116.66 6523.23,3116.66 6670.94,3264.37 6670.94,3406.61 6662.94,3414.61 6560.07,3414.61 U23.12@6559.38,3415.3
2.5Vref: C133.2 C134.1 C135.1 C136.1 C137.1 C138.1 C139.2 C140.2 C141.2 C142.2 C143.2 C144.2 C145.2 C146.2 C147.2 C148.2 C149.2 C150.2 C151.1 C160.2 J5.1 J_2V5.1 U15.3 U15.5 U15.10 U15.12 U16.3 U16.7 U17.3 U17.7 U18.3 U18.7 U19.3 U19.5 U19.10 U19.12 U20.3 U20.7 U21.3 U21.7 U22.3 U22.7 U25.3 U25.7 | length 4129.1
  Top Layer w14: v2(6463.44,1748.78) 6464.58,1747.63 6464.58,1741.44 6492.29,1713.73 C139.2@6494.26,1713.73 ; U19.12@6604.71,1665.26 6542.73,1665.26 C139.2@6494.26,1713.73 ; U19.10@6604.71,1765.26 6544.81,1765.26 6525.76,1746.22 6525.76,1745.23 C139.2@6494.26,1713.73 ; U19.3@7005.79,1665.26 7080.03,1665.26 7098.52,1646.77 7100.49,1646.77 7132.54,1678.82 v2(7132.54,1680.25) ; U19.5@7005.79,1765.26 7080.82,1765.26 7098.84,1783.28 7100.81,1783.28 7131.19,1813.66 v2(7131.19,1815.45) ; v2(7545.77,2105.25) 7546.92,2106.4 7548.85,2106.4 7581.12,2138.67 C147.2@7581.12,2139.66 7590.81,2149.35 7590.81,2236.13 U15.3@7592.08,2237.41 ; U15.12@7592.08,2638.49 7592.08,2670.42 7610.58,2688.92 7610.58,2708.59 C144.2@7642.08,2740.09 ; v2(7676.96,2773.17) 7675.81,2772.02 7672.04,2772.02 7642.08,2742.06 C144.2@7642.08,2741.08 C144.2@7642.08,2740.09 ; v2(7687.47,2107.78) 7688.62,2108.93 7691.47,2108.93 7721.11,2138.57 C146.2@7721.11,2139.55 7709.41,2151.25 7709.41,2158.64 7692.08,2175.97 U15.5@7692.08,2237.41 ; U15.10@7692.08,2638.49 7692.08,2670.42 7673.58,2688.92 7673.58,2708.59 C144.2@7642.08,2740.09
  Power w36: 6115.37,1097.74 6162.23,1144.6 ; 6151.31,889.74 6151.31,1101.02 ; 6198.16,1147.88 6321.31,1147.88 6352.37,1178.93 6352.37,1211.42 6342.4,1221.38 6342.4,1499.88 6463.44,1620.92 v2(6463.44,1748.78)
  Bottom Layer w20: v2(5600.36,1110.18) 5600.36,1101.13 C142.2@5637.48,1064.01 5707.64,1064.01 U25.3@5712.82,1069.19 ; U25.7@6073.05,1019.19 6120.92,1019.19 6142.86,1041.13 6205.26,1041.13 6205.88,1041.75 6205.88,1049.99 6234.56,1049.99 v2(6254.69,1070.11) ; U17.7@6633.19,1019.19 6690.85,1019.19 6704.69,1033.03 6762.57,1033.03 6798.73,1069.19 U20.3@6833.1,1069.19 ; U20.7@7193.33,1019.19 7247.8,1019.19 7261.64,1033.03 7326.67,1033.03 7362.83,1069.19 U22.3@7393.24,1069.19 ; U22.7@7757.91,1019.19 7758.77,1020.05 C138.1@7835.13,1020.05 7837.57,1017.6 v2(7837.57,975.51) ; U21.3@8208.53,2837.77 8208.53,2775.95 8204.78,2772.2 8204.78,2750.05 8222.08,2750.05 8232.63,2739.51 8232.63,2731.42 8260.57,2703.47 U18.7@8260.57,2636.14 ; U16.3@8210.57,1713.33 8210.57,1608.24 C149.2@8213.26,1605.56 8213.26,1581.6 J_2V5.1@8255.21,1539.65 ; U18.3@8210.57,2275.9 8211.17,2275.31 C150.2@8211.17,2201.68 8211.17,2200.83 8247.02,2164.98 8263.19,2164.98 C133.2@8263.19,2144.46 ; U21.7@8258.53,3198 8258.53,3274.45 8250.75,3282.23 8293.72,3282.23 v2(8302.41,3273.54) ; U16.7@8260.57,2073.57 8260.57,2141.84 C133.2@8263.19,2144.46 ; C135.1@8260.57,2713.35 8335.03,2713.35 v2(8338.88,2709.49) ; v2(8311.84,2138.05) 8305.43,2144.46 C133.2@8263.19,2144.46
  other v2: 7261.64,1029.09 6758.07,1035.42
2V: U12.4 | length 49.3
  Top Layer w20: U12.4@4728.53,2236.7 4763.39,2236.7 v1(4773.62,2226.47)
2V5_EN: Q37.1 Q41.1 U1.6 | length 3476.4
  Top Layer w10: U1.6@7574.97,3357.01 7728.84,3357.01 8106.7,2979.14 8106.7,2135.84 8122.57,2119.97 8122.57,1640.07 ; Q37.1@7603.69,1114.75 7603.69,1158.47 8083.04,1637.82 8120.32,1637.82 8122.57,1640.07 ; Q41.1@8448.04,1281.5 8530.01,1363.47 8530.01,1435.96 8363.78,1602.19 8160.44,1602.19 8122.57,1640.07
3.3V: C1.1 C2.1 C37.1 C38.1 C39.1 C42.1 C43.1 C44.1 C47.1 C48.1 C49.1 J1.2 J_3V3.2 Q42.2 R21.2 R49.2 R52.2 R56.2 R63.2 U1.37 U1.48 U8.5 U8.6 U10.5 U10.6 U12.5 U12.6 | length 4642.1
  Top Layer w20: U10.5@4354.92,1413.82 U10.6@4392.32,1413.82 4421.31,1442.8 v1(4421.31,1485.74) 4438.24,1468.8 4450.45,1468.8 4475.24,1444.01 R52.2@4475.24,1431.8 ; R49.2@4718.15,2845.27 4718.15,2843.58 4733.15,2828.58 v1(4774.29,2828.58) ; U12.5@4728.53,2199.3 U12.6@4728.53,2161.89 4745.48,2144.94 v1(4745.48,2139.26) 4745.48,2093.44 R56.2@4733.06,2081.02 ; v5(5849.29,2897.72) 5849.48,2897.91 5920.47,2897.91 R63.2@5920.67,2898.1
  Power w36: v1(4421.31,1485.74) 4421.31,1511.98 v1(4746.27,1836.95) 4817.28,1907.96 4817.28,2283.37 4737.62,2363.02 4737.62,2668.45 4774.29,2705.12 v1(4774.29,2828.58) ; v1(4955.9,2890.09) 4971.23,2905.42 v4(5321.71,2905.42) ; 5379.91,2794.13 5379.91,2878.58 5733.2,3231.86 v1(6412.33,3231.86)
  Bottom Layer w20: C43.1@4379.97,1437.48 4379.97,1444.41 v1(4421.31,1485.74) 4468.55,1438.5 C42.1@4468.55,1437.48 C44.1@4555.99,1437.48 ; U8.5@4647.75,2837.09 4670.22,2837.09 ; U8.6@4672.35,2844.97 4672.35,2880.27 4699.81,2907.74 C38.1@4706.31,2907.74 ; U8.6@4682.03,2844.97 4757.9,2844.97 v1(4774.29,2828.58) ; C38.1@4706.92,2907.13 C37.1@4800.4,2907.13 ; v1(4745.48,2139.26) 4746.09,2138.65 C48.1@4746.09,2077.52 C47.1@4746.09,1989.7 4746.27,1989.52 C49.1@4746.27,1900.51 v1(4746.27,1836.95) ; C37.1@4800.85,2906.69 4893.15,2906.69 C39.1@4893.6,2906.24 4908.6,2891.24 4954.75,2891.24 v1(4955.9,2890.09)
  other v1: 6444.33,3231.86 6476.33,3231.86
  other v2: 7282.89,3092.84 7734.88,3203.8
  other v4: 5321.49,2704.58 5386.62,2704.58 5321.71,2750.95 5386.85,2750.95 5386.85,2905.42
3.3V_2: C7.1 C8.1 I2C_pull.1 J_3V3_2.2 U2.13 | length 699.1
  Top Layer w20: v5(6866.36,2959.15) 6866.36,2954.82 6857.73,2946.19 6857.73,2906.81 C7.1@6842.73,2891.81 C8.1@6842.73,2788.32 6842.73,2781.82 6865.61,2758.93 6869.18,2758.93 6880.9,2747.22 U2.13@6880.9,2675.88
  Power w36: 6747.58,3113.03 6842.37,3018.24 6894.61,3070.49 I2C_pull.1@7001.62,3070.49 ; 6849.52,3025.4 6849.52,2975.98 v5(6866.36,2959.15)
3V3_EN: C164.2 Q42.1 R21.1 U1.28 | length 1166.2
  Top Layer w10: v6(7133.47,3456.29) 7134.61,3455.15 7147.99,3455.15 7188.4,3414.75 7291.59,3414.75 7292.62,3415.78 7306.98,3415.78 U1.28@7307.26,3416.06
  Bottom Layer w10: R21.1@6444.46,3094.49 6540.49,3094.49 C164.2@6548.81,3086.17 ; Q42.1@6548.67,3154.17 6548.81,3154.03 6548.81,3094.49 C164.2@6548.81,3086.17 ; v6(7133.47,3456.29) 7133.03,3456.29 6697.84,3021.1 6602.07,3021.1 6557.75,3065.42 6548.81,3074.36 6548.81,3080.26 C164.2@6548.81,3086.17
5Vcc: C5.1 C6.1 C26.1 C40.1 C41.1 C45.1 C46.1 C79.1 C107.1 C154.1 J4.1 J_5V.2 Q35.2 R45.2 R46.2 R47.2 R54.2 U2.2 U6.1 U6.2 U6.3 U6.4 U9.6 U11.6 U15.4 U19.4 | length 10482.3
  Top Layer w14: U19.4@7005.79,1715.26 7006.55,1714.5 7098.74,1714.5 C154.1@7099.51,1713.73 7100.49,1713.73 7128.62,1741.86 7128.62,1745.27 v2(7129.77,1746.41) ; v2(7616.38,2109.71) 7617.53,2110.86 7622.98,2110.86 7650.35,2138.23 C107.1@7650.35,2139.21 7643.35,2146.21 7643.35,2236.13 U15.4@7642.08,2237.41
  Top Layer w20: v1(4114.35,1568.25) 4093.07,1546.97 C45.1@4093.07,1508.85 C46.1@4162.54,1508.85 4175.26,1496.14 4194.59,1476.8 4199.54,1471.85 4199.54,1469.89 4212.43,1457.01 U11.6@4212.43,1366.74 ; v1(4412.03,2988.6) 4411.14,2987.71 4411.14,2944.8 4397.01,2930.67 4397.01,2840.47 C41.1@4397.87,2839.61 4397.87,2846.11 4412.87,2861.11 4422.04,2861.11 v1(4454.61,2893.67) ; R45.2@4483.88,3872.79 4490.38,3872.79 4562.08,3944.49 4721.81,3944.49 v1(4725.93,3940.36) ; R46.2@4661.99,1459.02 4661.99,1400.12 v1(4662.82,1399.29) ; Q35.2@4714.75,3347.64 v1(4714.75,3397.46) ; R47.2@4940.34,3301.83 4940.34,3304.65 4955.34,3319.65 v1(4990.16,3319.65) ; R54.2@5192,3027.11 5204.41,3039.52 v1(5246.06,3039.52) ; U6.1@5573.86,2259.64 U6.2@5623.86,2259.64 U6.3@5673.86,2259.64 U6.4@5723.86,2259.64 5723.86,2242.52 5767.09,2199.3 C26.1@5851.84,2199.3 5854.93,2202.39 5943.52,2202.39 C79.1@5946.62,2205.49 6310.75,2205.49 J_5V.2@6505.13,2011.11 6566.44,2011.11 6677.22,2121.89 6718.54,2121.89 C6.1@6731.41,2134.77 6746.37,2149.73 6746.37,2211.34 C5.1@6751.49,2216.45 6752.47,2216.45 6761.17,2225.15 6761.17,2256.55 6780.9,2276.27 U2.2@6780.9,2305.8
  Power w36: v1(4662.82,1399.29) 4901.85,1638.32 4908.25,1638.32 4908.25,1875.52 4912.19,1879.46 4912.19,2332.6 4915.1,2335.51 ; v1(4714.75,3397.46) 4727.42,3410.14 4895.04,3410.14 4903.09,3418.19 ; v1(4725.93,3940.36) 4738.6,3953.04 4848.93,3953.04 4858.89,3943.08 ; 4834.19,3093.38 4903.09,3162.28 4903.09,3418.19 ; 4836.8,3093.38 4836.8,2335.51 4915.1,2335.51 ; J4.1@5935.04,3798.15 5925.48,3807.71 5907.51,3807.71 5904.39,3810.83 5632.49,3810.83 5500.24,3943.08 4858.89,3943.08 ; J_5V.2@6505.13,2011.11 6505.13,2074.22 6361.95,2217.4 6054.39,2217.4 5936.28,2335.51 4915.1,2335.51 ; J_5V.2@6514.25,2004.13 6673.6,2004.13 6918.64,1759.09 7071.49,1759.09 ; v2(7129.77,1746.41) 7117.09,1759.09 7071.49,1759.09 ; v2(7616.38,2109.71) 7616.38,2123.9 7577.37,2162.91 7405.27,2162.91 7071.49,1829.13 7071.49,1759.09 ; 4858.89,3943.08 4903.09,3898.88 4903.09,3418.19
  Bottom Layer w20: v1(4454.61,2893.67) 4473.93,2874.35 U9.6@4473.93,2787.05
  other v5: 6430.84,2110.86 6561.1,2110.86 6626.24,2110.86 6495.97,2176 6561.1,2176 6626.24,2176
12V: "Supply Sel.2" C13.2 C14.2 C21.2 C22.2 C34.1 R10.2 U3.1 U3.2 U3.3 U3.4 U26.1 U26.2 U26.3 U26.4 | length 678.3
  Top Layer w20: 4920.66,1067.72 5034.39,1181.46 5034.39,1262.65 C14.2@5024.39,1272.65 ; C14.2@5018.97,1272.65 C14.2@5024.39,1272.65 ; U3.4@5410.77,1223.58 U3.3@5360.77,1223.58 U3.2@5310.77,1223.58 U3.1@5260.77,1223.58 5260.77,1240.58 5230.2,1271.16 C13.2@5167.48,1271.16 5166.73,1271.9 5097.64,1271.9 C22.2@5096.89,1272.65 C14.2@5024.39,1272.65
  other v7: 5232.66,1158.05 5298.15,1158.05 5363.64,1158.05
12V_EN: U1.29 U3.6 | length 3360.6
  Top Layer w10: v6(7139.5,3433.06) 7175.81,3396.75 7284.83,3396.75 7284.92,3396.65 7306.98,3396.65 U1.29@7307.26,3396.38
  Top Layer w20: v1(5510.4,1275.09) 5510.77,1274.71 U3.6@5510.77,1223.58
  Bottom Layer w10: v1(5510.4,1275.09) 5651.64,1275.09 5841.19,1464.63 6002.26,1464.63 6355.97,1818.34 6355.97,2295.98 6464.58,2404.59 6464.58,2952.93 6506.73,2995.08 6539.26,2995.08 6540.26,2996.08 6613.71,2996.08 6614.71,2995.08 6703.61,2995.08 7120.74,3412.22 7120.74,3414.31 v6(7139.5,3433.06)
